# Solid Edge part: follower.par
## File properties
Author: Deepak Maini
Template: normal.par
Last saved by: CADCIM
Revision: 6
Application: Solid Edge
Accuracy: 0.99
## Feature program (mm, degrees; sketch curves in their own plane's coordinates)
sketch for "unnamed Protrusion 1" plane through (0, 0, 18.8714) normal (0, 0, 1) x-axis (1, 0, 0)
  line (-78.836, 27.8599) -> (-22.3427, 36.4287)
  arc centre (-20.5076, 24.3301) radius 12.2369 from (-22.3427, 36.4287) to (-20.5076, 12.0932) cw
  line (-77.6471, 12.0932) -> (-20.5076, 12.0932)
  arc centre (-77.6471, 20.0214) radius 7.9282 from (-77.6471, 12.0932) to (-78.836, 27.8599) cw
extrude "unnamed Protrusion 1" add finite 8.5604 along +normal
sketch for "ExtrudedProtrusion_2" plane through (0, 0, -11.35) normal (0, 0, 1) x-axis (1, 0, 0)
  circle centre (-20.5076, 24.3301) radius 3.5
extrude "ExtrudedProtrusion_2" add along +normal  Plane_Distance = 11.35 mm
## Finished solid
Body 1: solid body, 8 faces, 14 edges, 8 vertices.
  Faces by surface: plane 5, cylinder 3
  Edges by curve: line 8, circle 6
Bounding box of the edges (mm): 77.305 x 24.474 x 38.782, from (-85.5752, 12.0932, -11.35) to (-8.2707, 36.567, 27.4319).
Cylindrical faces by radius (mm): R3.5 x1, R7.9282 x1, R12.2369 x1
Planar faces by outward normal: +z 1, -y 1, -z 2, oblique 1
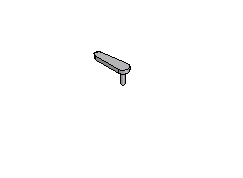
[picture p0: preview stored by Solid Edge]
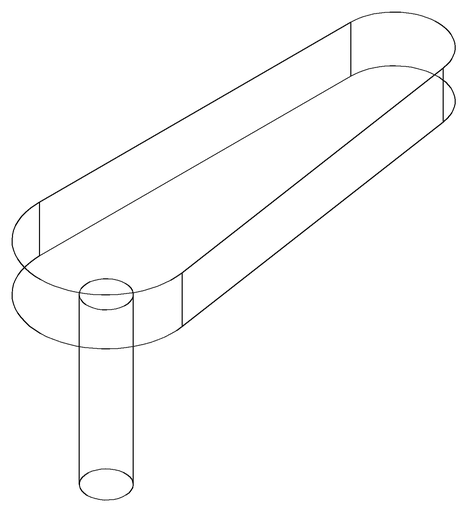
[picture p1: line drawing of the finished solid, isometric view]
